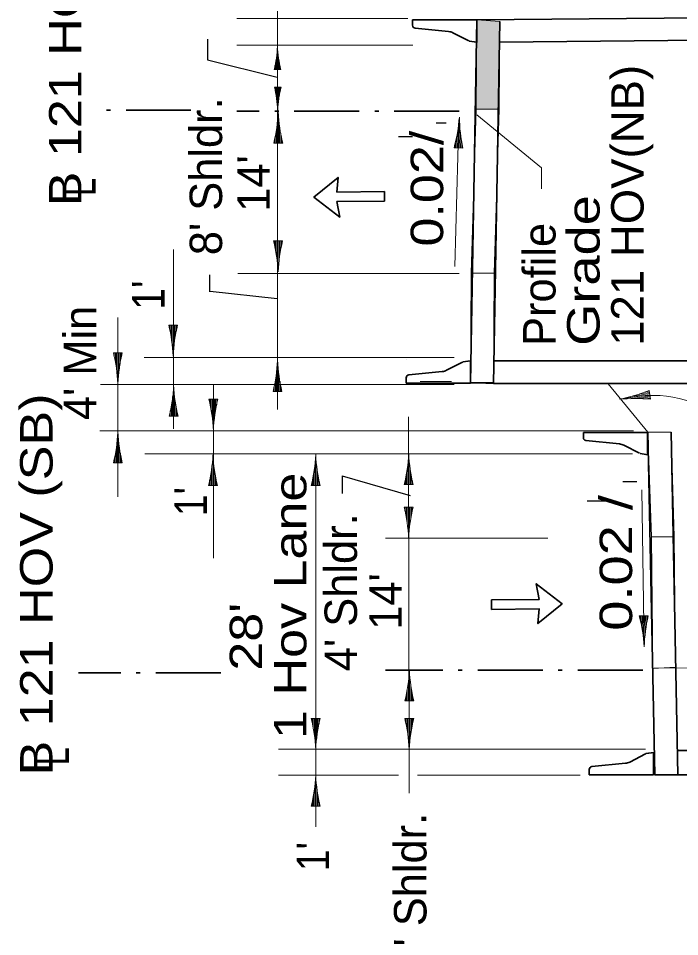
# Model space of a CAD drawing. Extents: x 2363427 to 2368559, y 6957299 to 6980140.
# Drawn here: x 2364990.1 to 2365275.3, y 6965257.3 to 6965653.5 of the extents above; entities that cross this region are included whole.
import ezdxf
from ezdxf.enums import TextEntityAlignment as Align

# ---------------------------------------------------------------- set-up
doc = ezdxf.new("R2010")
doc.units = 0
doc.header["$LTSCALE"] = 5.6
doc.linetypes.add('DOT_DASHED', pattern=[7.7, 5, -1.2, 0.3, -1.2])
doc.layers.add('3', color=7, linetype='Continuous', lineweight=35)
doc.layers.add('4', color=7, linetype='Continuous', lineweight=13)

msp = doc.modelspace()

# ---------------------------------------------------------------- hatches: boundary and pattern name
at = {"layer": '3'}
msp.add_hatch(color=256, dxfattribs=at).paths.add_polyline_path([(2365187.519, 6965614.409), (2365197.446, 6965614.409), (2365197.823, 6965652.168), (2365187.823, 6965652.844)])

# ---------------------------------------------------------------- linework, layer by layer
for p, q in [((2365160.103, 6965652.844), (2365160.103, 6965650.53)), ((2365187.823, 6965652.844), (2365160.103, 6965652.844)), ((2365187.823, 6965652.844), (2365185.086, 6965496.218)), ((2365187.823, 6965652.844), (2365408.405, 6965654.874)), ((2365187.823, 6965643.214), (2365187.823, 6965652.844)), ((2365197.823, 6965652.168), (2365195.092, 6965495.856)), ((2365161.209, 6965649.306), (2365175.692, 6965647.854)), ((2365177.523, 6965647.312), (2365184.357, 6965643.798)), ((2365197.657, 6965643.304), (2365410.85, 6965645.266)), ((2365184.525, 6965643.732), (2365184.535, 6965643.706)), ((2365127.47, 6965578.602), (2365147.975, 6965578.796)), ((2365195.264, 6965505.702), (2365330.94, 6965505.702)), ((2365174.788, 6965501.682), (2365181.623, 6965505.196)), ((2365181.791, 6965505.262), (2365181.801, 6965505.288)), ((2365157.368, 6965496.15), (2365157.368, 6965498.464)), ((2365158.474, 6965499.686), (2365172.958, 6965501.14)), ((2365195.087, 6965496.218), (2365185.086, 6965496.218)), ((2365195.094, 6965496.006), (2365333.387, 6965496.006)), ((2365233.791, 6965474.906), (2365233.791, 6965472.592)), ((2365261.603, 6965474.94), (2365261.871, 6965461.494)), ((2365271.603, 6965475.04), (2365274.555, 6965327.142)), ((2365234.897, 6965471.37), (2365249.38, 6965469.916)), ((2365251.211, 6965469.374), (2365258.045, 6965465.86)), ((2365258.213, 6965465.794), (2365258.223, 6965465.768)), ((2365261.871, 6965461.494), (2365264.551, 6965327.142)), ((2365214.742, 6965398.738), (2365194.237, 6965398.542)), ((2365253.767, 6965332.662), (2365260.602, 6965336.176)), ((2365260.77, 6965336.244), (2365260.78, 6965336.27)), ((2365264.067, 6965336.76), (2365264.067, 6965327.13)), ((2365274.223, 6965337.598), (2365395.875, 6965337.598)), ((2365237.453, 6965330.668), (2365251.937, 6965332.12)), ((2365236.347, 6965327.13), (2365236.347, 6965329.446)), ((2365264.067, 6965327.13), (2365236.347, 6965327.13)), ((2365274.402, 6965327.142), (2365264.399, 6965327.142)), ((2365274.402, 6965327.142), (2365397.842, 6965327.142))]:
    msp.add_line(p, q, dxfattribs=at)
at = {"layer": '3', "linetype": 'DOT_DASHED'}
for p, q in [((2365064.542, 6965613.917), (2365026.023, 6965613.917)), ((2365180.228, 6965613.418), (2365084.298, 6965613.418)), ((2365077.378, 6965371.21), (2365016.013, 6965371.21))]:
    msp.add_line(p, q, dxfattribs=at)
at = {"layer": '3', "lineweight": 13}
for p, q in [((2365215.703, 6965588.966), (2365187.779, 6965611.896)), ((2365215.703, 6965579.994), (2365215.703, 6965588.966)), ((2365261.603, 6965474.94), (2365244.461, 6965495.84)), ((2365261.603, 6965474.94), (2365271.603, 6965475.04)), ((2365360.157, 6965374.341), (2365264.185, 6965373.111))]:
    msp.add_line(p, q, dxfattribs=at)
for points in [[(2365187.519, 6965614.409), (2365197.446, 6965614.409), (2365197.823, 6965652.168), (2365187.823, 6965652.844)], [(2365185.392, 6965543.552), (2365195.319, 6965543.552), (2365197.446, 6965614.409), (2365187.519, 6965614.409)], [(2365185.086, 6965496.218), (2365195.092, 6965495.856), (2365195.319, 6965543.552), (2365185.392, 6965543.552)], [(2365263.196, 6965429.83), (2365272.938, 6965429.83), (2365271.603, 6965475.04), (2365261.603, 6965474.94)], [(2365263.737, 6965373.033), (2365273.48, 6965373.574), (2365272.938, 6965429.83), (2365263.196, 6965429.83)], [(2365264.551, 6965327.142), (2365274.555, 6965327.142), (2365273.48, 6965373.574), (2365263.737, 6965373.033)]]:
    msp.add_lwpolyline(points, close=True, dxfattribs=at)
at = {"layer": '3'}
for points in [[(2365184.737, 6965643.676), (2365187.877, 6965643.206), (2365184.535, 6965643.706)], [(2365127.47, 6965578.602), (2365128.002, 6965584.916), (2365117.615, 6965576.382), (2365128.715, 6965567.78), (2365127.507, 6965574.506)], [(2365127.507, 6965574.506), (2365148.012, 6965574.702), (2365147.975, 6965578.796)], [(2365185.088, 6965505.78), (2365185.088, 6965496.15), (2365157.368, 6965496.15)], [(2365182.002, 6965505.318), (2365185.142, 6965505.788), (2365181.801, 6965505.288)], [(2365261.511, 6965465.276), (2365261.511, 6965474.906), (2365233.791, 6965474.906)], [(2365258.425, 6965465.738), (2365261.565, 6965465.268), (2365258.223, 6965465.768)], [(2365214.742, 6965398.738), (2365214.21, 6965392.422), (2365224.597, 6965400.958), (2365213.497, 6965409.56), (2365214.705, 6965402.832)], [(2365214.705, 6965402.832), (2365194.2, 6965402.638), (2365194.237, 6965398.542)], [(2365260.981, 6965336.298), (2365264.121, 6965336.768), (2365260.78, 6965336.27)]]:
    msp.add_lwpolyline(points, dxfattribs=at)
for points in [[(2365117.615, 6965576.382), (2365128.002, 6965584.916), (2365127.47, 6965578.602), (2365147.975, 6965578.796), (2365148.012, 6965574.702), (2365127.507, 6965574.506), (2365128.715, 6965567.78)], [(2365224.597, 6965400.958), (2365214.21, 6965392.422), (2365214.742, 6965398.738), (2365194.237, 6965398.542), (2365194.2, 6965402.638), (2365214.705, 6965402.832), (2365213.497, 6965409.56)]]:
    msp.add_lwpolyline(points, close=True, dxfattribs=at)
for centre, radius, start, end in [((2365161.332, 6965650.53), 1.229, 180, 264.27822), ((2365175.181, 6965642.76), 5.12, 62.77128, 84.26462), ((2365172.446, 6965506.234), 5.12, 275.73538, 297.22872), ((2365158.597, 6965498.465), 1.229, 95.72178, 180), ((2365235.02, 6965472.592), 1.229, 180, 264.27822), ((2365248.869, 6965464.823), 5.12, 62.77128, 84.26462), ((2365251.426, 6965337.215), 5.12, 275.73538, 297.22872), ((2365237.576, 6965329.446), 1.229, 95.72178, 180)]:
    msp.add_arc(centre, radius, start, end, dxfattribs=at)
at = {"layer": '3', "lineweight": 13}
msp.add_arc((2365263.479, 6965438.389), 52.473, 55.82294, 104.54523, dxfattribs=at)
at = {"layer": '4'}
for p, q in [((2365101.88, 6965484.726), (2365101.88, 6965670.724)), ((2365158.127, 6965653.418), (2365084.289, 6965653.418)), ((2365160.202, 6965642.01), (2365084.314, 6965642.01)), ((2365101.909, 6965631.444), (2365101.909, 6965640.868)), ((2365101.534, 6965631.444), (2365101.534, 6965637.902)), ((2365102.284, 6965631.444), (2365102.284, 6965636.956)), ((2365100.784, 6965631.444), (2365100.784, 6965633.23)), ((2365101.159, 6965631.444), (2365101.159, 6965635.09)), ((2365102.659, 6965631.444), (2365102.659, 6965634.652)), ((2365103.034, 6965631.444), (2365103.034, 6965632.634)), ((2365103.296, 6965631.444), (2365100.424, 6965631.444)), ((2365100.541, 6965623.888), (2365103.415, 6965623.888)), ((2365100.804, 6965623.888), (2365100.804, 6965622.7)), ((2365101.179, 6965623.888), (2365101.179, 6965620.681)), ((2365101.554, 6965623.888), (2365101.554, 6965618.376)), ((2365101.929, 6965623.888), (2365101.929, 6965614.465)), ((2365102.304, 6965623.888), (2365102.304, 6965617.431)), ((2365102.679, 6965623.888), (2365102.679, 6965620.242)), ((2365103.054, 6965623.888), (2365103.054, 6965622.102)), ((2365102.258, 6965599.71), (2365102.258, 6965612.274)), ((2365178.331, 6965546.436), (2365180.126, 6965609.72)), ((2365179.984, 6965597.594), (2365180.341, 6965610.152)), ((2365101.258, 6965599.71), (2365101.258, 6965604.572)), ((2365101.758, 6965599.71), (2365101.758, 6965608.32)), ((2365102.758, 6965599.71), (2365102.758, 6965607.06)), ((2365179.485, 6965597.608), (2365179.729, 6965606.214)), ((2365180.484, 6965597.58), (2365180.693, 6965604.926)), ((2365100.758, 6965599.71), (2365100.758, 6965602.092)), ((2365103.258, 6965599.71), (2365103.258, 6965603.988)), ((2365103.758, 6965599.71), (2365103.758, 6965601.296)), ((2365178.985, 6965597.622), (2365179.123, 6965602.482)), ((2365180.984, 6965597.566), (2365181.105, 6965601.84)), ((2365104.108, 6965599.71), (2365100.278, 6965599.71)), ((2365181.834, 6965597.542), (2365178.005, 6965597.65)), ((2365178.485, 6965597.636), (2365178.553, 6965600.016)), ((2365181.484, 6965597.552), (2365181.529, 6965599.136)), ((2365100.219, 6965557.51), (2365104.049, 6965557.51)), ((2365100.569, 6965557.51), (2365100.569, 6965555.925)), ((2365101.069, 6965557.51), (2365101.069, 6965553.234)), ((2365101.569, 6965557.51), (2365101.569, 6965550.16)), ((2365102.069, 6965557.51), (2365102.069, 6965544.946)), ((2365102.569, 6965557.51), (2365102.569, 6965548.9)), ((2365103.069, 6965557.51), (2365103.069, 6965552.648)), ((2365103.569, 6965557.51), (2365103.569, 6965555.128)), ((2365057.093, 6965553.855), (2365057.093, 6965476.369)), ((2365180.228, 6965543.418), (2365084.71, 6965543.418)), ((2365033.041, 6965524.532), (2365033.041, 6965447.046)), ((2365054.965, 6965521.147), (2365058.795, 6965521.147)), ((2365055.315, 6965521.147), (2365055.315, 6965519.562)), ((2365055.815, 6965521.147), (2365055.815, 6965516.87)), ((2365056.315, 6965521.147), (2365056.315, 6965513.797)), ((2365056.815, 6965521.147), (2365056.815, 6965508.583)), ((2365057.315, 6965521.147), (2365057.315, 6965512.538)), ((2365057.815, 6965521.147), (2365057.815, 6965516.285)), ((2365058.315, 6965521.147), (2365058.315, 6965518.766)), ((2365031.108, 6965509.222), (2365034.938, 6965509.222)), ((2365031.458, 6965509.222), (2365031.458, 6965507.638)), ((2365031.958, 6965509.222), (2365031.958, 6965504.946)), ((2365032.458, 6965509.222), (2365032.458, 6965501.872)), ((2365032.958, 6965509.222), (2365032.958, 6965496.658)), ((2365033.458, 6965509.222), (2365033.458, 6965500.613)), ((2365033.958, 6965509.222), (2365033.958, 6965504.36)), ((2365034.458, 6965509.222), (2365034.458, 6965506.841)), ((2365178.032, 6965507.196), (2365044.383, 6965507.196)), ((2365157.395, 6965506.32), (2365157.395, 6965506.366)), ((2365101.957, 6965492.588), (2365101.957, 6965505.152)), ((2365100.957, 6965492.588), (2365100.957, 6965497.45)), ((2365101.457, 6965492.588), (2365101.457, 6965501.198)), ((2365102.457, 6965492.588), (2365102.457, 6965499.938)), ((2365178.032, 6965495.619), (2365025.511, 6965495.619)), ((2365057.158, 6965481.822), (2365057.158, 6965494.386)), ((2365074.233, 6965495.598), (2365074.233, 6965420.587)), ((2365100.457, 6965492.588), (2365100.457, 6965494.97)), ((2365102.957, 6965492.588), (2365102.957, 6965496.864)), ((2365103.457, 6965492.588), (2365103.457, 6965494.172)), ((2365176.904, 6965496.78), (2365163.377, 6965496.78)), ((2365056.658, 6965481.822), (2365056.658, 6965490.43)), ((2365103.807, 6965492.588), (2365099.977, 6965492.588)), ((2365262.469, 6965491.154), (2365250.039, 6965489.335)), ((2365262.543, 6965490.66), (2365254.024, 6965489.412)), ((2365262.397, 6965491.65), (2365255.125, 6965490.585)), ((2365262.614, 6965490.166), (2365257.803, 6965489.461)), ((2365262.325, 6965492.144), (2365258.093, 6965491.524)), ((2365262.687, 6965489.67), (2365260.331, 6965489.326)), ((2365262.253, 6965492.638), (2365260.684, 6965492.409)), ((2365262.202, 6965492.986), (2365262.757, 6965489.196)), ((2365056.158, 6965481.822), (2365056.158, 6965486.684)), ((2365057.658, 6965481.822), (2365057.658, 6965489.172)), ((2365058.158, 6965481.822), (2365058.158, 6965486.098)), ((2365072.296, 6965489.162), (2365076.126, 6965489.162)), ((2365072.646, 6965489.162), (2365072.646, 6965487.578)), ((2365073.146, 6965489.162), (2365073.146, 6965484.886)), ((2365073.646, 6965489.162), (2365073.646, 6965481.812)), ((2365074.146, 6965489.162), (2365074.146, 6965476.598)), ((2365074.646, 6965489.162), (2365074.646, 6965480.553)), ((2365075.146, 6965489.162), (2365075.146, 6965484.3)), ((2365075.646, 6965489.162), (2365075.646, 6965486.781)), ((2365059.008, 6965481.822), (2365055.178, 6965481.822)), ((2365055.658, 6965481.822), (2365055.658, 6965484.202)), ((2365058.658, 6965481.822), (2365058.658, 6965483.406)), ((2365158.724, 6965319.222), (2365158.44, 6965481.568)), ((2365255.419, 6965475.498), (2365025.316, 6965475.498)), ((2365033.105, 6965461.686), (2365033.105, 6965474.25)), ((2365032.605, 6965461.686), (2365032.605, 6965470.296)), ((2365032.105, 6965461.686), (2365032.105, 6965466.548)), ((2365033.605, 6965461.686), (2365033.605, 6965469.036)), ((2365034.105, 6965461.686), (2365034.105, 6965465.962)), ((2365031.605, 6965461.686), (2365031.605, 6965464.068)), ((2365034.605, 6965461.686), (2365034.605, 6965463.272)), ((2365254.974, 6965465.702), (2365044.68, 6965465.702)), ((2365074.108, 6965451.932), (2365074.108, 6965464.496)), ((2365118.365, 6965304.702), (2365118.365, 6965465.678)), ((2365118.431, 6965451.932), (2365118.431, 6965464.496)), ((2365158.533, 6965452.39), (2365158.533, 6965464.954)), ((2365034.955, 6965461.686), (2365031.125, 6965461.686)), ((2365073.608, 6965451.932), (2365073.608, 6965460.54)), ((2365074.608, 6965451.932), (2365074.608, 6965459.282)), ((2365117.931, 6965451.932), (2365117.931, 6965460.54)), ((2365118.931, 6965451.932), (2365118.931, 6965459.282)), ((2365158.033, 6965452.39), (2365158.033, 6965461)), ((2365159.033, 6965452.39), (2365159.033, 6965459.74)), ((2365072.608, 6965451.932), (2365072.608, 6965454.312)), ((2365073.108, 6965451.932), (2365073.108, 6965456.794)), ((2365075.108, 6965451.932), (2365075.108, 6965456.208)), ((2365116.931, 6965451.932), (2365116.931, 6965454.312)), ((2365117.431, 6965451.932), (2365117.431, 6965456.794)), ((2365118.454, 6965456.442), (2365118.454, 6965457.728)), ((2365119.431, 6965451.932), (2365119.431, 6965456.208)), ((2365157.033, 6965452.39), (2365157.033, 6965454.772)), ((2365157.533, 6965452.39), (2365157.533, 6965457.252)), ((2365159.533, 6965452.39), (2365159.533, 6965456.668)), ((2365160.033, 6965452.39), (2365160.033, 6965453.976)), ((2365075.958, 6965451.932), (2365072.128, 6965451.932)), ((2365075.608, 6965451.932), (2365075.608, 6965453.516)), ((2365120.281, 6965451.932), (2365116.451, 6965451.932)), ((2365119.931, 6965451.932), (2365119.931, 6965453.516)), ((2365160.383, 6965452.39), (2365156.553, 6965452.39)), ((2365260.027, 6965382.415), (2365258.953, 6965450.132)), ((2365156.495, 6965442.57), (2365160.325, 6965442.57)), ((2365156.845, 6965442.57), (2365156.845, 6965440.985)), ((2365157.345, 6965442.57), (2365157.345, 6965438.294)), ((2365157.845, 6965442.57), (2365157.845, 6965435.22)), ((2365158.345, 6965442.57), (2365158.345, 6965430.006)), ((2365158.845, 6965442.57), (2365158.845, 6965433.96)), ((2365159.345, 6965442.57), (2365159.345, 6965437.708)), ((2365159.845, 6965442.57), (2365159.845, 6965440.188)), ((2365218.525, 6965429.258), (2365148.463, 6965429.258)), ((2365257.901, 6965395.695), (2365261.731, 6965395.755)), ((2365258.251, 6965395.7), (2365258.276, 6965394.115)), ((2365258.751, 6965395.708), (2365258.819, 6965391.432)), ((2365259.251, 6965395.716), (2365259.368, 6965388.367)), ((2365259.751, 6965395.724), (2365259.95, 6965383.161)), ((2365260.251, 6965395.732), (2365260.388, 6965387.123)), ((2365260.751, 6965395.74), (2365260.828, 6965390.879)), ((2365261.251, 6965395.748), (2365261.289, 6965393.367)), ((2365158.811, 6965359.008), (2365158.811, 6965371.572)), ((2365158.311, 6965359.008), (2365158.311, 6965367.618)), ((2365157.811, 6965359.008), (2365157.811, 6965363.87)), ((2365159.311, 6965359.008), (2365159.311, 6965366.358)), ((2365159.811, 6965359.008), (2365159.811, 6965363.286)), ((2365160.661, 6965359.008), (2365156.831, 6965359.008)), ((2365157.311, 6965359.008), (2365157.311, 6965361.39)), ((2365160.311, 6965359.008), (2365160.311, 6965360.594)), ((2365116.451, 6965351.494), (2365120.281, 6965351.494)), ((2365116.801, 6965351.494), (2365116.801, 6965349.908)), ((2365117.301, 6965351.494), (2365117.301, 6965347.218)), ((2365117.801, 6965351.494), (2365117.801, 6965344.144)), ((2365118.301, 6965351.494), (2365118.301, 6965338.93)), ((2365118.801, 6965351.494), (2365118.801, 6965342.884)), ((2365119.301, 6965351.494), (2365119.301, 6965346.632)), ((2365119.801, 6965351.494), (2365119.801, 6965349.112)), ((2365156.775, 6965351.494), (2365160.605, 6965351.494)), ((2365157.125, 6965351.494), (2365157.125, 6965349.909)), ((2365157.625, 6965351.494), (2365157.625, 6965347.218)), ((2365158.125, 6965351.494), (2365158.125, 6965344.144)), ((2365158.625, 6965351.494), (2365158.625, 6965338.93)), ((2365159.125, 6965351.494), (2365159.125, 6965342.884)), ((2365159.625, 6965351.494), (2365159.625, 6965346.632)), ((2365160.125, 6965351.494), (2365160.125, 6965349.112)), ((2365260.611, 6965338.182), (2365102.295, 6965338.182)), ((2365154.1, 6965326.932), (2365102.295, 6965326.932)), ((2365118.431, 6965313.62), (2365118.431, 6965326.184)), ((2365232.428, 6965326.932), (2365162.256, 6965326.932)), ((2365117.931, 6965313.62), (2365117.931, 6965322.23)), ((2365118.931, 6965313.62), (2365118.931, 6965320.97)), ((2365116.931, 6965313.62), (2365116.931, 6965316.002)), ((2365117.431, 6965313.62), (2365117.431, 6965318.482)), ((2365119.431, 6965313.62), (2365119.431, 6965317.898)), ((2365119.931, 6965313.62), (2365119.931, 6965315.206)), ((2365120.281, 6965313.62), (2365116.451, 6965313.62))]:
    msp.add_line(p, q, dxfattribs=at)
at = {"layer": '4', "lineweight": 25}
for p, q in [((2365170.376, 6965608.404), (2365174.662, 6965608.404)), ((2365160.091, 6965602.409), (2365154.091, 6965602.409)), ((2365072.599, 6965542.928), (2365072.599, 6965535.572)), ((2365072.77, 6965535.76), (2365101.759, 6965532.71)), ((2365129.813, 6965456.198), (2365129.813, 6965448.58)), ((2365129.813, 6965456.198), (2365159.105, 6965447.604)), ((2365250.807, 6965453.73), (2365256.806, 6965453.73)), ((2365243.95, 6965445.165), (2365235.417, 6965445.165))]:
    msp.add_line(p, q, dxfattribs=at)
at = {"layer": '4', "linetype": 'DOT_DASHED', "lineweight": 35}
msp.add_line((2365259.385, 6965372.32), (2365148.463, 6965372.32), dxfattribs=at)
at = {"layer": '4', "lineweight": 25}
msp.add_lwpolyline([(2365071.624, 6965644.59), (2365071.624, 6965635.702), (2365101.788, 6965628.192)], dxfattribs=at)
at = {"layer": '4'}
for centre, radius, start, end in [((2365047.768, 6965644.116), 54.159, 346.47039, 357.15644), ((2365155.953, 6965644.116), 54.159, 182.84356, 193.52961), ((2365047.886, 6965611.218), 54.159, 2.84356, 13.52961), ((2365156.071, 6965611.218), 54.159, 166.47039, 177.15644), ((2365030.069, 6965616.606), 72.212, 346.47039, 357.15644), ((2365174.316, 6965616.606), 72.212, 182.84356, 193.52961), ((2365108.305, 6965616.528), 72.212, 344.84626, 355.53231), ((2365252.494, 6965612.439), 72.212, 181.21943, 191.90548), ((2365030.011, 6965540.617), 72.212, 2.84356, 13.52961), ((2365174.258, 6965540.617), 72.212, 166.47039, 177.15644), ((2364984.757, 6965504.254), 72.212, 2.84356, 13.52961), ((2365129.004, 6965504.254), 72.212, 166.47039, 177.15644), ((2364960.9, 6965492.329), 72.212, 2.84356, 13.52961), ((2365105.147, 6965492.329), 72.212, 166.47039, 177.15644), ((2365029.768, 6965509.483), 72.212, 346.47039, 357.15644), ((2365174.015, 6965509.483), 72.212, 182.84356, 193.52961), ((2364984.97, 6965498.716), 72.212, 346.47039, 357.15644), ((2365129.217, 6965498.716), 72.212, 182.84356, 193.52961), ((2365235.317, 6965560.007), 72.212, 281.17215, 291.8582), ((2365256.212, 6965417.281), 72.212, 84.79899, 95.48504), ((2365002.088, 6965472.269), 72.212, 2.84356, 13.52961), ((2365146.335, 6965472.269), 72.212, 166.47039, 177.15644), ((2364960.917, 6965478.581), 72.212, 346.47039, 357.15644), ((2365105.164, 6965478.581), 72.212, 182.84356, 193.52961), ((2365001.92, 6965468.826), 72.212, 346.47039, 357.15644), ((2365146.167, 6965468.826), 72.212, 182.84356, 193.52961), ((2365046.242, 6965468.826), 72.212, 346.47039, 357.15644), ((2365190.49, 6965468.826), 72.212, 182.84356, 193.52961), ((2365086.345, 6965469.285), 72.212, 346.47039, 357.15644), ((2365230.592, 6965469.285), 72.212, 182.84356, 193.52961), ((2365086.287, 6965425.677), 72.212, 2.84356, 13.52961), ((2365230.534, 6965425.677), 72.212, 166.47039, 177.15644), ((2365187.97, 6965377.69), 72.212, 3.7522, 14.43825), ((2365332.199, 6965379.978), 72.212, 167.37903, 178.06508), ((2365086.623, 6965375.904), 72.212, 346.47039, 357.15644), ((2365230.87, 6965375.904), 72.212, 182.84356, 193.52961), ((2365046.242, 6965334.601), 72.212, 2.84356, 13.52961), ((2365190.489, 6965334.601), 72.212, 166.47039, 177.15644), ((2365086.567, 6965334.601), 72.212, 2.84356, 13.52961), ((2365230.814, 6965334.601), 72.212, 166.47039, 177.15644), ((2365046.242, 6965330.516), 72.212, 346.47039, 357.15644), ((2365190.49, 6965330.516), 72.212, 182.84356, 193.52961)]:
    msp.add_arc(centre, radius, start, end, dxfattribs=at)

# ---------------------------------------------------------------- texts
for s, width, p in [('B 121 HOV (NB)', 1.2, (2365017.335, 6965655.458)), ('0.02/', 1.2, (2365173.332, 6965580.06)), ('L', 0.75, (2365023.462, 6965580.822)), ("1' ", 0.9, (2365053.154, 6965536.47)), ('B 121 HOV (SB)', 1.2, (2365004.869, 6965409.276)), ('1 Hov Lane', 1.2, (2365114.334, 6965400.086)), ("1' ", 0.9, (2365071.437, 6965447.372)), ('0.02 /', 1.25, (2365254.827, 6965418.586)), ("28'", 1.2, (2365095.264, 6965386.712)), ('L', 0.75, (2365011.993, 6965335.076)), ("1' ", 0.9, (2365124.123, 6965294.201))]:
    msp.add_text(s, height=14, rotation=90, dxfattribs=dict(at, width=width)).set_placement(p, align=Align.CENTER)
for s, width, p in [('121 HOV(NB)', 1.05, (2365259.782, 6965512.216)), ('Grade ', 1.25, (2365240.782, 6965512.216))]:
    msp.add_text(s, height=14, rotation=90, dxfattribs=dict(at, width=width)).set_placement(p)
for s, p in [("8' Shldr.", (2365077.987, 6965585.382)), ("14'", (2365098.529, 6965582.275)), ("4' Min", (2365023.722, 6965504.844)), ("4' Shldr.", (2365136.169, 6965405.896)), ("14'", (2365155.44, 6965401.939)), ("8' Shldr.", (2365166.124, 6965276.694))]:
    msp.add_text(s, height=14, rotation=90, dxfattribs=at).set_placement(p, align=Align.CENTER)
msp.add_text('Profile ', height=14, rotation=90, dxfattribs=at).set_placement((2365221.782, 6965512.216))

doc.saveas('drawing.dxf')
